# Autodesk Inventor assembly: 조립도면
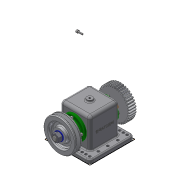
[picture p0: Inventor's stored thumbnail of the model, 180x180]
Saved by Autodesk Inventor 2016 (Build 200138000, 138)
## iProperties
Created: 2018-11
Part Number: 조립도면
Material: 일반
Document SubType Name: Assembly
Designer: 605-04
Author: 605-04
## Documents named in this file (13)
- C:\Users\605-04\Desktop\481108V1001\조립도면.iam
- C:\Users\605-04\Desktop\481108V1001\본체.ipt
- C:\Users\605-04\Desktop\481108V1001\축.ipt
- C:\Users\605-04\Desktop\481108V1001\키 5x5x12.ipt
- C:\Users\605-04\Desktop\481108V1001\커버.ipt
- C:\Users\605-04\Desktop\481108V1001\와셔 12x24.ipt
- C:\Users\605-04\Desktop\481108V1001\스퍼기어.ipt
- C:\Users\605-04\Desktop\481108V1001\베어링 6203.ipt
- C:\Users\605-04\Desktop\481108V1001\V벨트풀리.ipt
- C:\Users\605-04\Desktop\481108V1001\오일 실 26 38 8.ipt
- C:\Users\605-04\Desktop\481108V1001\부시.ipt
- C:\Users\605-04\Desktop\481108V1001\볼트 M4.ipt
- C:\Users\605-04\Desktop\481108V1001\너트 M12x1.25.ipt
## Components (1 placed, 1 different names)
1. V벨트풀리:1 — 각도:1
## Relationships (1: Angle 1)
- 각도:1 [Angle]: V벨트풀리:1
